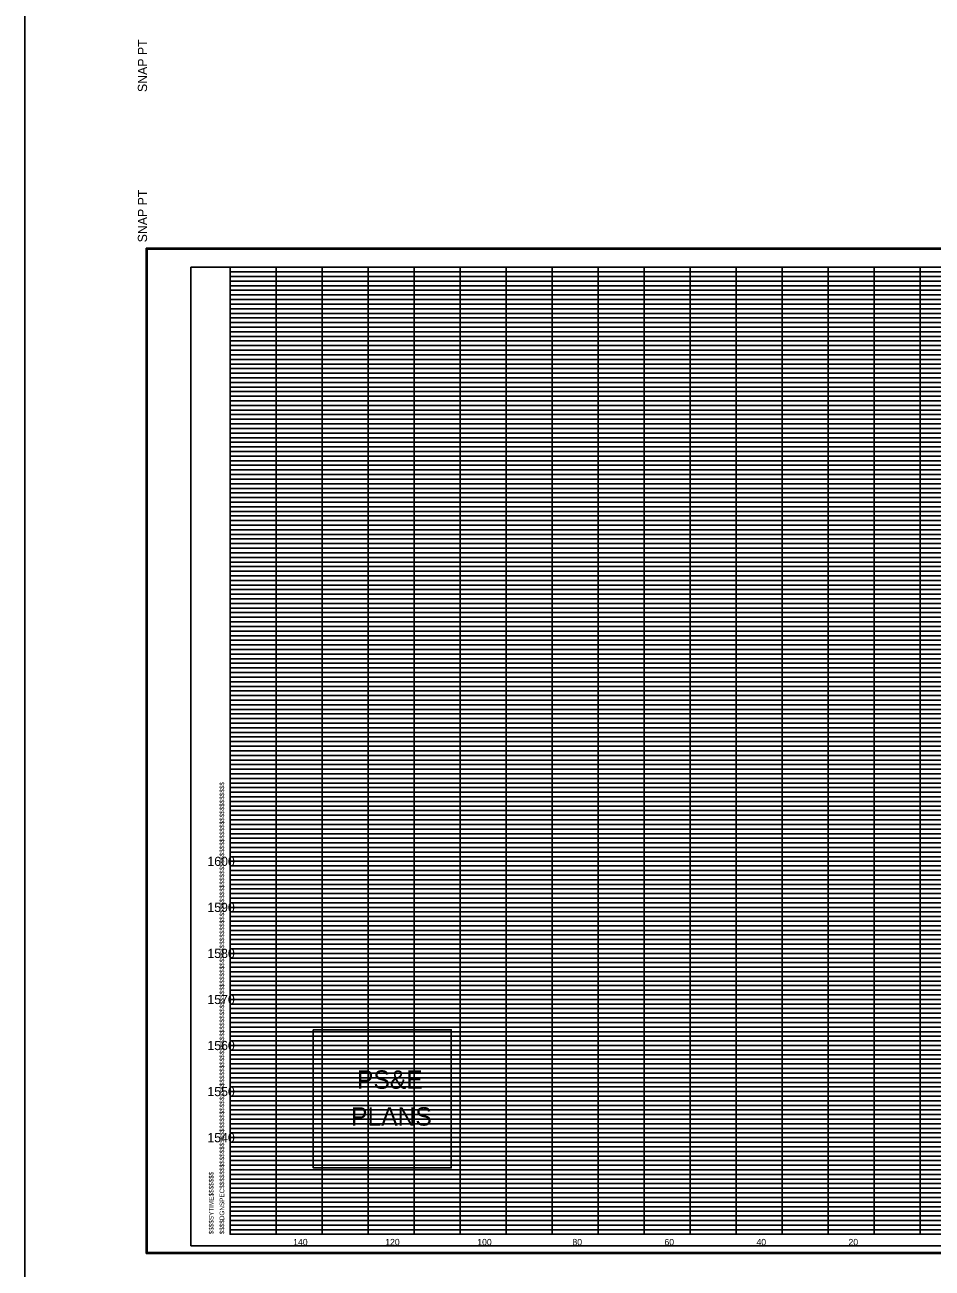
# Model space of a CAD drawing. Extents: x 955 to 1375, y 1248 to 3657.
# Drawn here: x 955.4 to 1152.6, y 1802.7 to 2072.7 of the extents above; entities that cross this region are included whole.
import ezdxf

# ---------------------------------------------------------------- set-up
doc = ezdxf.new("R2010")
doc.units = 0
for name, color, linetype in [('DESIGN - SHEET - Corner Text', 7, 'Continuous'), ('DESIGN - SHEET - Light Grid', 7, 'Continuous'), ('DESIGN - SHEET - Linework', 7, 'Continuous'), ('DESIGN - SHEET - Plot Shape', 7, 'Continuous'), ('DESIGN - TYPICAL - Text', 7, 'Continuous'), ('DESIGN - UTILITIES - Cable (Overhead) with Text', 7, 'Continuous'), ('SURVEY - NON-TRANSPORTATION - Features Text', 7, 'Continuous')]:
    doc.layers.add(name, color=color, linetype=linetype)

# ---------------------------------------------------------------- blocks, each defined once
blk = doc.blocks.new('XSTSHT')
at = {"layer": 'DESIGN - SHEET - Light Grid'}
for p, q in [((0, 20.9), (8, 20.9)), ((0, 20.8), (8, 20.8)), ((8, 20.9), (16, 20.9)), ((8, 20.8), (16, 20.8)), ((0, 20.7), (8, 20.7)), ((0, 20.6), (8, 20.6)), ((8, 20.7), (16, 20.7)), ((8, 20.6), (16, 20.6)), ((0, 20.5), (8, 20.5)), ((0, 20.4), (8, 20.4)), ((0, 20.3), (8, 20.3)), ((8, 20.5), (16, 20.5)), ((8, 20.4), (16, 20.4)), ((8, 20.3), (16, 20.3)), ((0, 20.2), (8, 20.2)), ((0, 20.1), (8, 20.1)), ((8, 20.2), (16, 20.2)), ((8, 20.1), (16, 20.1)), ((0, 19.9), (8, 19.9)), ((0, 19.8), (8, 19.8)), ((8, 19.9), (16, 19.9)), ((8, 19.8), (16, 19.8)), ((0, 19.7), (8, 19.7)), ((0, 19.6), (8, 19.6)), ((0, 19.5), (8, 19.5)), ((8, 19.7), (16, 19.7)), ((8, 19.6), (16, 19.6)), ((8, 19.5), (16, 19.5)), ((0, 19.4), (8, 19.4)), ((0, 19.3), (8, 19.3)), ((0, 19.2), (8, 19.2)), ((8, 19.4), (16, 19.4)), ((8, 19.3), (16, 19.3)), ((8, 19.2), (16, 19.2)), ((0, 19.1), (8, 19.1)), ((8, 19.1), (16, 19.1)), ((0, 18.9), (8, 18.9)), ((0, 18.8), (8, 18.8)), ((0, 18.7), (8, 18.7)), ((8, 18.9), (16, 18.9)), ((8, 18.8), (16, 18.8)), ((8, 18.7), (16, 18.7)), ((0, 18.6), (8, 18.6)), ((0, 18.5), (8, 18.5)), ((0, 18.4), (8, 18.4)), ((8, 18.6), (16, 18.6)), ((8, 18.5), (16, 18.5)), ((8, 18.4), (16, 18.4)), ((0, 18.3), (8, 18.3)), ((0, 18.2), (8, 18.2)), ((0, 18.1), (8, 18.1)), ((8, 18.3), (16, 18.3)), ((8, 18.2), (16, 18.2)), ((8, 18.1), (16, 18.1)), ((0, 17.9), (8, 17.9)), ((8, 17.9), (16, 17.9)), ((0, 17.8), (8, 17.8)), ((0, 17.7), (8, 17.7)), ((0, 17.6), (8, 17.6)), ((8, 17.8), (16, 17.8)), ((8, 17.7), (16, 17.7)), ((8, 17.6), (16, 17.6)), ((0, 17.5), (8, 17.5)), ((0, 17.4), (8, 17.4)), ((0, 17.3), (8, 17.3)), ((8, 17.5), (16, 17.5)), ((8, 17.4), (16, 17.4)), ((8, 17.3), (16, 17.3)), ((0, 17.2), (8, 17.2)), ((0, 17.1), (8, 17.1)), ((8, 17.2), (16, 17.2)), ((8, 17.1), (16, 17.1)), ((0, 16.9), (8, 16.9)), ((0, 16.8), (8, 16.8)), ((8, 16.9), (16, 16.9)), ((8, 16.8), (16, 16.8)), ((0, 16.7), (8, 16.7)), ((0, 16.6), (8, 16.6)), ((0, 16.5), (8, 16.5)), ((8, 16.7), (16, 16.7)), ((8, 16.6), (16, 16.6)), ((8, 16.5), (16, 16.5)), ((0, 16.4), (8, 16.4)), ((0, 16.3), (8, 16.3)), ((8, 16.4), (16, 16.4)), ((8, 16.3), (16, 16.3)), ((0, 16.2), (8, 16.2)), ((0, 16.1), (8, 16.1)), ((8, 16.2), (16, 16.2)), ((8, 16.1), (16, 16.1)), ((0, 15.9), (8, 15.9)), ((0, 15.8), (8, 15.8)), ((0, 15.7), (8, 15.7)), ((8, 15.9), (16, 15.9)), ((8, 15.8), (16, 15.8)), ((8, 15.7), (16, 15.7)), ((0, 15.6), (8, 15.6)), ((0, 15.5), (8, 15.5)), ((0, 15.4), (8, 15.4)), ((8, 15.6), (16, 15.6)), ((8, 15.5), (16, 15.5)), ((8, 15.4), (16, 15.4)), ((0, 15.3), (8, 15.3)), ((0, 15.2), (8, 15.2)), ((8, 15.3), (16, 15.3)), ((8, 15.2), (16, 15.2)), ((0, 15.1), (8, 15.1)), ((0, 14.9), (8, 14.9)), ((8, 15.1), (16, 15.1)), ((8, 14.9), (16, 14.9)), ((0, 14.8), (8, 14.8)), ((0, 14.7), (8, 14.7)), ((0, 14.6), (8, 14.6)), ((8, 14.8), (16, 14.8)), ((8, 14.7), (16, 14.7)), ((8, 14.6), (16, 14.6)), ((0, 14.5), (8, 14.5)), ((0, 14.4), (8, 14.4)), ((8, 14.5), (16, 14.5)), ((8, 14.4), (16, 14.4)), ((0, 14.3), (8, 14.3)), ((0, 14.2), (8, 14.2)), ((0, 14.1), (8, 14.1)), ((8, 14.3), (16, 14.3)), ((8, 14.2), (16, 14.2)), ((8, 14.1), (16, 14.1)), ((0, 13.9), (8, 13.9)), ((0, 13.8), (8, 13.8)), ((8, 13.9), (16, 13.9)), ((8, 13.8), (16, 13.8)), ((0, 13.7), (8, 13.7)), ((0, 13.6), (8, 13.6)), ((8, 13.7), (16, 13.7)), ((8, 13.6), (16, 13.6)), ((0, 13.5), (8, 13.5)), ((0, 13.4), (8, 13.4)), ((0, 13.3), (8, 13.3)), ((8, 13.5), (16, 13.5)), ((8, 13.4), (16, 13.4)), ((8, 13.3), (16, 13.3)), ((0, 13.2), (8, 13.2)), ((0, 13.1), (8, 13.1)), ((8, 13.2), (16, 13.2)), ((8, 13.1), (16, 13.1)), ((0, 12.9), (8, 12.9)), ((0, 12.8), (8, 12.8)), ((0, 12.7), (8, 12.7)), ((8, 12.9), (16, 12.9)), ((8, 12.8), (16, 12.8)), ((8, 12.7), (16, 12.7)), ((0, 12.6), (8, 12.6)), ((0, 12.5), (8, 12.5)), ((8, 12.6), (16, 12.6)), ((8, 12.5), (16, 12.5)), ((0, 12.4), (8, 12.4)), ((0, 12.3), (8, 12.3)), ((0, 12.2), (8, 12.2)), ((8, 12.4), (16, 12.4)), ((8, 12.3), (16, 12.3)), ((8, 12.2), (16, 12.2)), ((0, 12.1), (8, 12.1)), ((0, 11.9), (8, 11.9)), ((8, 12.1), (16, 12.1)), ((8, 11.9), (16, 11.9)), ((0, 11.8), (8, 11.8)), ((0, 11.7), (8, 11.7)), ((8, 11.8), (16, 11.8)), ((8, 11.7), (16, 11.7)), ((0, 11.6), (8, 11.6)), ((0, 11.5), (8, 11.5)), ((0, 11.4), (8, 11.4)), ((8, 11.6), (16, 11.6)), ((8, 11.5), (16, 11.5)), ((8, 11.4), (16, 11.4)), ((0, 11.3), (8, 11.3)), ((0, 11.2), (8, 11.2)), ((0, 11.1), (8, 11.1)), ((8, 11.3), (16, 11.3)), ((8, 11.2), (16, 11.2)), ((8, 11.1), (16, 11.1)), ((0, 10.9), (8, 10.9)), ((8, 10.9), (16, 10.9)), ((0, 10.8), (8, 10.8)), ((0, 10.7), (8, 10.7)), ((0, 10.6), (8, 10.6)), ((8, 10.8), (16, 10.8)), ((8, 10.7), (16, 10.7)), ((8, 10.6), (16, 10.6)), ((0, 10.5), (8, 10.5)), ((0, 10.4), (8, 10.4)), ((0, 10.3), (8, 10.3)), ((8, 10.5), (16, 10.5)), ((8, 10.4), (16, 10.4)), ((8, 10.3), (16, 10.3)), ((0, 10.2), (8, 10.2)), ((0, 10.1), (8, 10.1)), ((8, 10.2), (16, 10.2)), ((8, 10.1), (16, 10.1)), ((0, 9.9), (8, 9.9)), ((0, 9.8), (8, 9.8)), ((8, 9.9), (16, 9.9)), ((8, 9.8), (16, 9.8)), ((0, 9.7), (8, 9.7)), ((0, 9.6), (8, 9.6)), ((0, 9.5), (8, 9.5)), ((8, 9.7), (16, 9.7)), ((8, 9.6), (16, 9.6)), ((8, 9.5), (16, 9.5)), ((0, 9.4), (8, 9.4)), ((0, 9.3), (8, 9.3)), ((0, 9.2), (8, 9.2)), ((8, 9.4), (16, 9.4)), ((8, 9.3), (16, 9.3)), ((8, 9.2), (16, 9.2)), ((0, 9.1), (8, 9.1)), ((8, 9.1), (16, 9.1)), ((0, 8.9), (8, 8.9)), ((0, 8.8), (8, 8.8)), ((0, 8.7), (8, 8.7)), ((8, 8.9), (16, 8.9)), ((8, 8.8), (16, 8.8)), ((8, 8.7), (16, 8.7)), ((0, 8.6), (8, 8.6)), ((0, 8.5), (8, 8.5)), ((0, 8.4), (8, 8.4)), ((8, 8.6), (16, 8.6)), ((8, 8.5), (16, 8.5)), ((8, 8.4), (16, 8.4)), ((0, 8.3), (8, 8.3)), ((0, 8.2), (8, 8.2)), ((8, 8.3), (16, 8.3)), ((8, 8.2), (16, 8.2)), ((0, 8.1), (8, 8.1)), ((0, 7.9), (8, 7.9)), ((8, 8.1), (16, 8.1)), ((8, 7.9), (16, 7.9)), ((0, 7.8), (8, 7.8)), ((0, 7.7), (8, 7.7)), ((0, 7.6), (8, 7.6)), ((8, 7.8), (16, 7.8)), ((8, 7.7), (16, 7.7)), ((8, 7.6), (16, 7.6)), ((0, 7.5), (8, 7.5)), ((0, 7.4), (8, 7.4)), ((0, 7.3), (8, 7.3)), ((8, 7.5), (16, 7.5)), ((8, 7.4), (16, 7.4)), ((8, 7.3), (16, 7.3)), ((0, 7.2), (8, 7.2)), ((0, 7.1), (8, 7.1)), ((8, 7.2), (16, 7.2)), ((8, 7.1), (16, 7.1)), ((0, 6.9), (8, 6.9)), ((0, 6.8), (8, 6.8)), ((8, 6.9), (16, 6.9)), ((8, 6.8), (16, 6.8)), ((0, 6.7), (8, 6.7)), ((0, 6.6), (8, 6.6)), ((0, 6.5), (8, 6.5)), ((8, 6.7), (16, 6.7)), ((8, 6.6), (16, 6.6)), ((8, 6.5), (16, 6.5)), ((0, 6.4), (8, 6.4)), ((0, 6.3), (8, 6.3)), ((8, 6.4), (16, 6.4)), ((8, 6.3), (16, 6.3)), ((0, 6.2), (8, 6.2)), ((0, 6.1), (8, 6.1)), ((8, 6.2), (16, 6.2)), ((8, 6.1), (16, 6.1)), ((0, 5.9), (8, 5.9)), ((0, 5.8), (8, 5.8)), ((0, 5.7), (8, 5.7)), ((8, 5.9), (16, 5.9)), ((8, 5.8), (16, 5.8)), ((8, 5.7), (16, 5.7)), ((0, 5.6), (8, 5.6)), ((0, 5.5), (8, 5.5)), ((8, 5.6), (16, 5.6)), ((8, 5.5), (16, 5.5)), ((0, 5.4), (8, 5.4)), ((0, 5.3), (8, 5.3)), ((0, 5.2), (8, 5.2)), ((8, 5.4), (16, 5.4)), ((8, 5.3), (16, 5.3)), ((8, 5.2), (16, 5.2)), ((0, 5.1), (8, 5.1)), ((0, 4.9), (8, 4.9)), ((8, 5.1), (16, 5.1)), ((8, 4.9), (16, 4.9)), ((0, 4.8), (8, 4.8)), ((0, 4.7), (8, 4.7)), ((0, 4.6), (8, 4.6)), ((8, 4.8), (16, 4.8)), ((8, 4.7), (16, 4.7)), ((8, 4.6), (16, 4.6)), ((0, 4.5), (8, 4.5)), ((0, 4.4), (8, 4.4)), ((8, 4.5), (16, 4.5)), ((8, 4.4), (16, 4.4)), ((0, 4.3), (8, 4.3)), ((0, 4.2), (8, 4.2)), ((0, 4.1), (8, 4.1)), ((8, 4.3), (16, 4.3)), ((8, 4.2), (16, 4.2)), ((8, 4.1), (16, 4.1)), ((0, 3.9), (8, 3.9)), ((0, 3.8), (8, 3.8)), ((8, 3.9), (16, 3.9)), ((8, 3.8), (16, 3.8)), ((0, 3.7), (8, 3.7)), ((0, 3.6), (8, 3.6)), ((8, 3.7), (16, 3.7)), ((8, 3.6), (16, 3.6)), ((0, 3.5), (8, 3.5)), ((0, 3.4), (8, 3.4)), ((0, 3.3), (8, 3.3)), ((8, 3.5), (16, 3.5)), ((8, 3.4), (16, 3.4)), ((8, 3.3), (16, 3.3)), ((0, 3.2), (8, 3.2)), ((0, 3.1), (8, 3.1)), ((8, 3.2), (16, 3.2)), ((8, 3.1), (16, 3.1)), ((0, 2.9), (8, 2.9)), ((0, 2.8), (8, 2.8)), ((8, 2.9), (16, 2.9)), ((8, 2.8), (16, 2.8)), ((0, 2.7), (8, 2.7)), ((0, 2.6), (8, 2.6)), ((0, 2.5), (8, 2.5)), ((8, 2.7), (16, 2.7)), ((8, 2.6), (16, 2.6)), ((8, 2.5), (16, 2.5)), ((0, 2.4), (8, 2.4)), ((0, 2.3), (8, 2.3)), ((0, 2.2), (8, 2.2)), ((8, 2.4), (16, 2.4)), ((8, 2.3), (16, 2.3)), ((8, 2.2), (16, 2.2)), ((0, 2.1), (8, 2.1)), ((0, 1.9), (8, 1.9)), ((8, 2.1), (16, 2.1)), ((8, 1.9), (16, 1.9)), ((0, 1.8), (8, 1.8)), ((0, 1.7), (8, 1.7)), ((8, 1.8), (16, 1.8)), ((8, 1.7), (16, 1.7)), ((0, 1.6), (8, 1.6)), ((0, 1.5), (8, 1.5)), ((0, 1.4), (8, 1.4)), ((8, 1.6), (16, 1.6)), ((8, 1.5), (16, 1.5)), ((8, 1.4), (16, 1.4)), ((0, 1.3), (8, 1.3)), ((0, 1.2), (8, 1.2)), ((0, 1.1), (8, 1.1)), ((8, 1.3), (16, 1.3)), ((8, 1.2), (16, 1.2)), ((8, 1.1), (16, 1.1)), ((0, 0.9), (8, 0.9)), ((8, 0.9), (16, 0.9)), ((0, 0.8), (8, 0.8)), ((0, 0.7), (8, 0.7)), ((0, 0.6), (8, 0.6)), ((8, 0.8), (16, 0.8)), ((8, 0.7), (16, 0.7)), ((8, 0.6), (16, 0.6)), ((0, 0.5), (8, 0.5)), ((0, 0.4), (8, 0.4)), ((0, 0.3), (8, 0.3)), ((8, 0.5), (16, 0.5)), ((8, 0.4), (16, 0.4)), ((8, 0.3), (16, 0.3)), ((0, 0.2), (8, 0.2)), ((0, 0.1), (8, 0.1)), ((8, 0.2), (16, 0.2)), ((8, 0.1), (16, 0.1))]:
    blk.add_line(p, q, dxfattribs=at)
at = {"layer": 'DESIGN - SHEET - Linework'}
for p, q in [((-1.823, -0.414), (-1.823, 21.414)), ((-1.823, 21.414), (32.217, 21.414)), ((1, 0), (1, 21)), ((2, 0), (2, 21)), ((3, 0), (3, 21)), ((4, 0), (4, 21)), ((5, 0), (5, 21)), ((6, 0), (6, 21)), ((7, 0), (7, 21)), ((8, 0), (8, 21)), ((9, 0), (9, 21)), ((10, 0), (10, 21)), ((11, 0), (11, 21)), ((12, 0), (12, 21)), ((13, 0), (13, 21)), ((14, 0), (14, 21)), ((15, 0), (15, 21)), ((0, 20), (28, 20)), ((0, 19), (32, 19)), ((0, 18), (32, 18)), ((0, 17), (32, 17)), ((0, 16), (32, 16)), ((0, 15), (32, 15)), ((0, 14), (32, 14)), ((0, 13), (32, 13)), ((0, 12), (32, 12)), ((0, 11), (32, 11)), ((0, 10), (32, 10)), ((0, 9), (32, 9)), ((0, 8), (32, 8)), ((0, 7), (32, 7)), ((0, 6), (32, 6)), ((0, 5), (32, 5)), ((0, 4), (32, 4)), ((0, 3), (32, 3)), ((0, 2), (32, 2)), ((0, 1), (32, 1)), ((-1.823, -0.414), (32.217, -0.414))]:
    blk.add_line(p, q, dxfattribs=at)
blk.add_lwpolyline([(0, 21), (0, 0), (32, 0), (32, 21), (0, 21)], dxfattribs=at)
at = {"layer": 'DESIGN - SHEET - Plot Shape'}
for points in [[(-1.803, 21.394), (32.197, 21.394), (32.197, -0.394), (-1.803, -0.394)], [(-0.85, 21), (32, 21), (32, -0.25), (-0.85, -0.25)]]:
    blk.add_lwpolyline(points, close=True, dxfattribs=at)
at = {"layer": 'DESIGN - SHEET - Corner Text'}
for s, height, p in [('  SNAP PT', 0.2, (-1.803, 21.394)), ('$$$$DGNSPEC$$$$$$$$$$$$$$$$$$$$$$$$$$$$$$$$$$$$$$$$$$$$$$$$$$$$$$$$$$$$$$$$$$$$$$$$$$$$$$$$$$$$$$$$$$$$$$$$$$$$$$$$$$$$$$$$$$$', 0.100002, (-0.126, 0)), ('$$$$SYTIME$$$$$$$', 0.1, (-0.358, 0)), ('SNAP PT  ', 0.2, (-1.803, -2.194))]:
    blk.add_text(s, height=height, rotation=90, dxfattribs=at).set_placement(p)

msp = doc.modelspace()

# ---------------------------------------------------------------- linework, layer by layer
at = {"layer": 'DESIGN - SHEET - Corner Text'}
msp.add_lwpolyline([(1018.08, 1854.43), (1018.08, 1824.43), (1048.08, 1824.43), (1048.08, 1854.43)], close=True, dxfattribs=at)
at = {"layer": 'DESIGN - SHEET - Plot Shape'}
msp.add_lwpolyline([(991.5, 1807.5), (1320, 1807.5), (1320, 2020), (991.5, 2020)], close=True, dxfattribs=at)
at = {"layer": 'SURVEY - NON-TRANSPORTATION - Features Text'}
msp.add_lwpolyline([(955.41, 1505.76), (1344.98, 1505.76), (1344.98, 3398.01), (955.41, 3398.01)], close=True, dxfattribs=at)

# ---------------------------------------------------------------- block references
at = {"layer": 'DESIGN - UTILITIES - Cable (Overhead) with Text', "xscale": 10, "yscale": 10}
for p in [(1000, 2080), (1000, 1810)]:
    msp.add_blockref('XSTSHT', p, dxfattribs=at)

# ---------------------------------------------------------------- texts
at = {"layer": 'DESIGN - SHEET - Corner Text'}
for s, p in [('PS&E', (1027.6, 1841.6)), ('PLANS', (1026.31, 1833.6))]:
    msp.add_text(s, height=4, dxfattribs=at).set_placement(p)
at = {"layer": 'DESIGN - TYPICAL - Text'}
for s, height, p in [('     1600     ', 2, (991.37, 1890)), ('     1590     ', 2, (991.37, 1880)), ('     1580     ', 2, (991.37, 1870)), ('     1570     ', 2, (991.37, 1860)), ('     1560     ', 2, (991.37, 1850)), ('     1550     ', 2, (991.37, 1840)), ('     1540     ', 2, (991.37, 1830)), ('     140     ', 1.4, (1011.14, 1807.6)), ('     120     ', 1.4, (1031.14, 1807.6)), ('     100     ', 1.4, (1051.14, 1807.6)), ('     80     ', 1.4, (1071.82, 1807.6)), ('     60     ', 1.4, (1091.82, 1807.6)), ('     40     ', 1.4, (1111.82, 1807.6)), ('     20     ', 1.4, (1131.82, 1807.6))]:
    msp.add_text(s, height=height, dxfattribs=at).set_placement(p)

doc.saveas('drawing.dxf')
